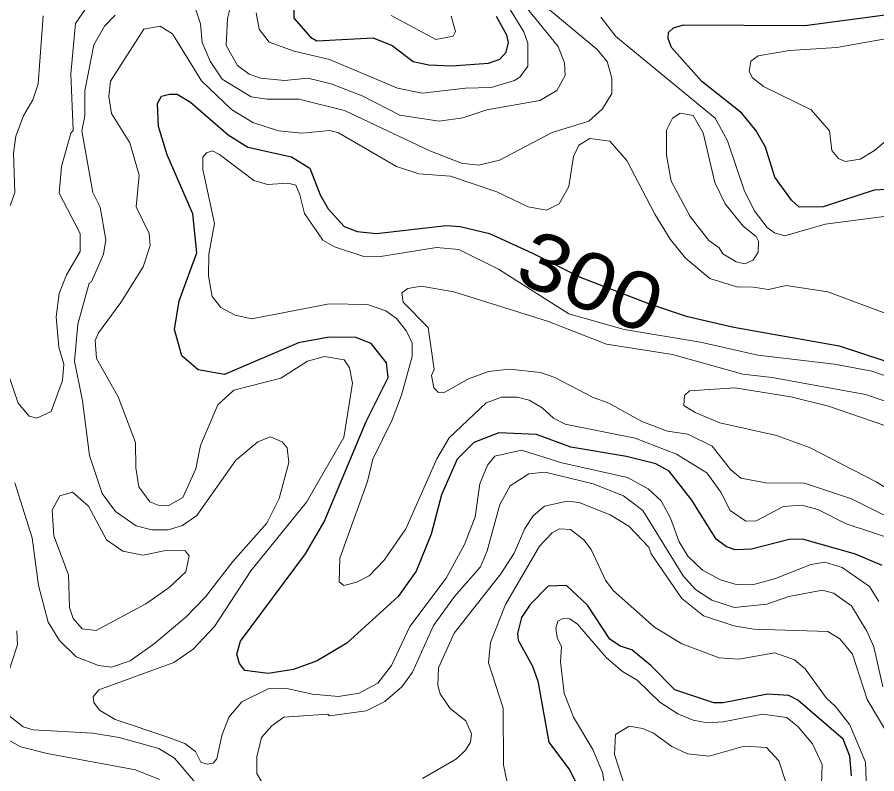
# Model space of a CAD drawing. Extents: x 673.6 to 698.9, y 7012 to 7040.1.
# Drawn here: x 677.012 to 678.22, y 7016.482 to 7017.545 of the extents above; entities that cross this region are included whole.
import ezdxf
from ezdxf.enums import TextEntityAlignment as Align

# ---------------------------------------------------------------- set-up
doc = ezdxf.new("R2010")
doc.units = 0
doc.header["$LTSCALE"] = 0.032
doc.layers.add('1', color=7, linetype='Continuous', lineweight=25)
doc.layers.add('2', color=7, linetype='Continuous', lineweight=13)
doc.layers.add('61', color=7, linetype='Continuous')

msp = doc.modelspace()

# ---------------------------------------------------------------- linework, layer by layer
at = {"layer": '1'}
for points in [[(677.401, 7017.5941), (677.4009, 7017.5438), (677.424, 7017.5172), (677.4332, 7017.5123), (677.5124, 7017.5164), (677.539, 7017.5057), (677.5685, 7017.4832), (677.5907, 7017.4781), (677.6225, 7017.477), (677.6745, 7017.4809), (677.6905, 7017.4863), (677.6991, 7017.496), (677.7025, 7017.5095), (677.7002, 7017.5202), (677.6855, 7017.5465)], [(678.2408, 7017.3035), (678.2165, 7017.302), (678.1451, 7017.2789), (678.111, 7017.2783), (678.1003, 7017.288), (678.0768, 7017.3203), (678.0641, 7017.3627), (678.051, 7017.3857), (678.0304, 7017.4103), (677.9744, 7017.455), (677.9317, 7017.5028), (677.9271, 7017.5152), (677.9277, 7017.5239), (677.9347, 7017.5304), (677.9487, 7017.5344), (678.119, 7017.5338), (678.2393, 7017.5494)], [(678.2277, 7016.7746), (678.1904, 7016.7902), (678.1159, 7016.8113), (678.097, 7016.8112), (678.0444, 7016.7973), (678.0214, 7016.7966), (678.0092, 7016.8007), (677.9943, 7016.8114), (677.9605, 7016.8661), (677.9286, 7016.9072), (677.9096, 7016.9173), (677.8686, 7016.9279), (677.7901, 7016.9408), (677.742, 7016.9585), (677.689, 7016.9608), (677.654, 7016.9473), (677.6304, 7016.9241), (677.6083, 7016.8739), (677.594, 7016.8184), (677.5729, 7016.7665), (677.5474, 7016.731), (677.4751, 7016.6654), (677.4336, 7016.6403), (677.4002, 7016.6284), (677.3647, 7016.6225), (677.3318, 7016.6267), (677.3242, 7016.6366), (677.3204, 7016.65), (677.3256, 7016.6683), (677.4169, 7016.7908), (677.4433, 7016.836), (677.5025, 7016.9771), (677.5334, 7017.039), (677.531, 7017.0595), (677.5094, 7017.0865), (677.4881, 7017.0948), (677.4503, 7017.0957), (677.4073, 7017.0873), (677.3034, 7017.0432), (677.2663, 7017.0497), (677.2433, 7017.0694), (677.2328, 7017.1064), (677.2397, 7017.1466), (677.2645, 7017.2141), (677.2589, 7017.2687), (677.2226, 7017.3516), (677.2102, 7017.3916), (677.2091, 7017.424), (677.2147, 7017.4341), (677.2259, 7017.4371), (677.2366, 7017.4373), (677.2555, 7017.426), (677.3083, 7017.3798), (677.3361, 7017.3624), (677.3973, 7017.3488), (677.4232, 7017.333)], [(677.4232, 7017.333), (677.4379, 7017.2957), (677.4492, 7017.276), (677.4714, 7017.2512), (677.4898, 7017.2442), (677.5169, 7017.2412)], [(677.5169, 7017.2412), (677.6147, 7017.2525), (677.6344, 7017.2511), (677.6759, 7017.241), (677.7363, 7017.2136), (677.8032, 7017.1799), (677.8994, 7017.1427), (677.9525, 7017.125), (678.0192, 7017.1094), (678.1673, 7017.0832), (678.2631, 7017.0518)], [(678.1848, 7016.4786), (678.1825, 7016.5066), (678.1733, 7016.5302), (678.1093, 7016.5853), (678.0967, 7016.5919), (678.0666, 7016.5935), (678.0046, 7016.5813), (677.9914, 7016.5813), (677.9365, 7016.5999), (677.9028, 7016.6341), (677.8761, 7016.6558), (677.8596, 7016.661), (677.8448, 7016.6709), (677.8135, 7016.7185), (677.7839, 7016.7463), (677.7583, 7016.7456), (677.7332, 7016.7198), (677.7207, 7016.7012), (677.715, 7016.6791), (677.7159, 7016.6697), (677.7362, 7016.633), (677.7436, 7016.612), (677.7594, 7016.5263), (677.7882, 7016.4872), (677.8004, 7016.4634)]]:
    msp.add_lwpolyline(points, dxfattribs=at)
at = {"layer": '2'}
for points in [[(677.3476, 7017.5512), (677.3518, 7017.5283), (677.3661, 7017.51), (677.4013, 7017.4975), (677.4509, 7017.4858), (677.5463, 7017.4455), (677.5811, 7017.4384), (677.6419, 7017.4457), (677.6784, 7017.4465), (677.711, 7017.4561), (677.7188, 7017.4613), (677.7298, 7017.4765), (677.7297, 7017.5087), (677.7243, 7017.5248), (677.678, 7017.6002)], [(677.1823, 7017.5567), (677.2343, 7017.5754), (677.2527, 7017.5722), (677.2629, 7017.5556), (677.2694, 7017.5358), (677.2717, 7017.5097)], [(677.3125, 7017.5639), (677.3074, 7017.5435), (677.3058, 7017.5053), (677.3217, 7017.4776), (677.338, 7017.4654), (677.3537, 7017.4597), (677.3875, 7017.4565), (677.4204, 7017.4597), (677.4533, 7017.4516), (677.4967, 7017.4349), (677.5499, 7017.4074), (677.6052, 7017.399), (677.6381, 7017.4039), (677.6722, 7017.4153), (677.7467, 7017.4281), (677.7703, 7017.4422), (677.7822, 7017.4631), (677.7814, 7017.4811), (677.7724, 7017.5041), (677.7086, 7017.5827)], [(677.1134, 7017.5648), (677.0935, 7017.5364), (677.0872, 7017.4659), (677.0904, 7017.386), (677.087, 7017.3821), (677.074, 7017.3352), (677.0706, 7017.2978), (677.1002, 7017.2411), (677.1002, 7017.2157), (677.0811, 7017.1832), (677.0706, 7017.157), (677.0666, 7017.1241), (677.0704, 7017.0812), (677.0771, 7017.0574), (677.0753, 7017.0345), (677.0597, 7016.9909), (677.0394, 7016.9815), (677.0284, 7016.9844), (677.0129, 7017.0026), (676.9995, 7017.0423)], [(677.2717, 7017.5097), (677.2833, 7017.4833), (677.2999, 7017.4582), (677.3406, 7017.4334), (677.3632, 7017.4302), (677.4076, 7017.4301), (677.4721, 7017.4141), (677.5921, 7017.3575), (677.6366, 7017.3401), (677.6602, 7017.3373), (677.6899, 7017.3445), (677.7639, 7017.383), (677.8156, 7017.3993), (677.8348, 7017.4164), (677.8479, 7017.4379), (677.848, 7017.4597), (677.8415, 7017.4832), (677.8269, 7017.5005), (677.7467, 7017.5668)], [(676.8012, 7017.5472), (676.7946, 7017.5254), (676.7913, 7017.4779), (676.7987, 7017.4318), (676.8103, 7017.4084), (676.8378, 7017.377), (676.9033, 7017.328), (676.9545, 7017.2784), (676.9716, 7017.2678), (676.9826, 7017.2668), (677.0023, 7017.2814), (677.0082, 7017.299), (677.0066, 7017.3541), (677.0099, 7017.378), (677.0204, 7017.4068), (677.0339, 7017.4293), (677.0411, 7017.4515), (677.0485, 7017.5472)], [(677.0083, 7016.8907), (677.0329, 7016.8135), (677.0419, 7016.7464), (677.0551, 7016.6947), (677.0711, 7016.6692), (677.0946, 7016.6463), (677.1259, 7016.6338), (677.1442, 7016.6314), (677.1704, 7016.6403), (677.2048, 7016.6646), (677.2493, 7016.7023), (677.2767, 7016.7306), (677.3148, 7016.7799), (677.3627, 7016.8342), (677.3802, 7016.8685), (677.3936, 7016.9191), (677.3912, 7016.94), (677.3845, 7016.9485), (677.3679, 7016.9552), (677.35, 7016.9485), (677.3191, 7016.9226), (677.2643, 7016.8448), (677.2443, 7016.8308), (677.2242, 7016.8245), (677.2009, 7016.8244), (677.1788, 7016.8304), (677.1498, 7016.8505), (677.131, 7016.8757), (677.1134, 7016.9292), (677.1035, 7017.0061), (677.0921, 7017.0616), (677.0971, 7017.1137), (677.113, 7017.1713), (677.1162, 7017.1731), (677.1333, 7017.2122), (677.1364, 7017.2322), (677.1284, 7017.2782), (677.1183, 7017.2989), (677.1028, 7017.3857), (677.1068, 7017.4068), (677.1069, 7017.4419), (677.1196, 7017.5065), (677.1345, 7017.5327), (677.1494, 7017.5482)], [(677.6219, 7017.5468), (677.6278, 7017.5252), (677.6249, 7017.5184), (677.6004, 7017.5141), (677.5374, 7017.5476)], [(677.8324, 7017.5455), (677.8536, 7017.5183), (677.9933, 7017.4032), (678.0105, 7017.3715), (678.0338, 7017.302), (678.0481, 7017.2734), (678.0662, 7017.2498), (678.0766, 7017.2423), (678.091, 7017.2379), (678.1479, 7017.2542), (678.2338, 7017.2658)], [(678.2422, 7017.1257), (678.1515, 7017.1591), (678.093, 7017.1679), (678.0683, 7017.1623), (678.0436, 7017.1663), (678.0252, 7017.1656), (677.9854, 7017.1781), (677.9516, 7017.2066), (677.93, 7017.2332), (677.9081, 7017.2683), (677.869, 7017.3437), (677.8448, 7017.3711), (677.8171, 7017.375), (677.8013, 7017.3652), (677.7939, 7017.3496), (677.7872, 7017.3072), (677.774, 7017.2831), (677.756, 7017.2741), (677.7304, 7017.2788), (677.686, 7017.2999), (677.6209, 7017.3217), (677.5766, 7017.325), (677.5452, 7017.3352), (677.4635, 7017.3827), (677.4514, 7017.3858), (677.412, 7017.3825), (677.3791, 7017.3856), (677.3432, 7017.3974), (677.3133, 7017.4154), (677.271, 7017.456), (677.2302, 7017.522), (677.2126, 7017.5327), (677.19, 7017.5287), (677.143, 7017.4553), (677.1405, 7017.434), (677.1443, 7017.4097), (677.1699, 7017.3687), (677.1831, 7017.3233), (677.1792, 7017.2785), (677.1971, 7017.2414), (677.1988, 7017.2244), (677.1887, 7017.1945), (677.1573, 7017.1443), (677.1259, 7017.1017), (677.1216, 7017.0907), (677.1233, 7017.0653), (677.1536, 7017.0118), (677.1782, 7016.9472), (677.1784, 7016.9117), (677.183, 7016.8851), (677.1984, 7016.8639), (677.21, 7016.8591), (677.2241, 7016.8583), (677.2448, 7016.8699), (677.2628, 7016.9105), (677.2696, 7016.9433), (677.294, 7017.0004), (677.3163, 7017.0208), (677.3826, 7017.0377), (677.4199, 7017.0619), (677.4437, 7017.0685), (677.4713, 7017.0637), (677.479, 7017.0525), (677.4831, 7017.0307), (677.4709, 7016.9542), (677.4184, 7016.8634), (677.3403, 7016.7668), (677.2892, 7016.6888), (677.2591, 7016.6571), (677.2318, 7016.638)], [(678.2567, 7017.3911), (678.2173, 7017.3581), (678.1972, 7017.3456), (678.1757, 7017.3425), (678.1664, 7017.3468), (678.1572, 7017.3578), (678.1537, 7017.3854), (678.1282, 7017.4153), (678.0611, 7017.4479), (678.0457, 7017.4602), (678.0407, 7017.4691), (678.0435, 7017.4833), (678.0538, 7017.491), (678.0978, 7017.4983), (678.1643, 7017.5025), (678.2642, 7017.5206)], [(678.2487, 7016.8096), (678.1772, 7016.8329), (678.1373, 7016.8532), (678.1152, 7016.8591), (678.0893, 7016.8572), (678.0509, 7016.8372), (678.0361, 7016.8369), (678.0141, 7016.8517), (678.0011, 7016.8776), (677.9813, 7016.9047), (677.9388, 7016.9312), (677.8806, 7016.9536), (677.782, 7016.9734), (677.7657, 7016.9816), (677.7497, 7016.996), (677.7317, 7017.0068), (677.7149, 7017.011), (677.6929, 7017.011), (677.6712, 7017.0031), (677.6189, 7016.9541), (677.6017, 7016.9243), (677.5583, 7016.826), (677.5278, 7016.782), (677.5065, 7016.7598), (677.4892, 7016.751), (677.4712, 7016.7465), (677.4644, 7016.7516), (677.4654, 7016.7849), (677.5044, 7016.8924), (677.5119, 7016.9239), (677.5389, 7016.9795), (677.5521, 7017.014), (677.567, 7017.0685), (677.567, 7017.087), (677.5592, 7017.1037), (677.5451, 7017.1216), (677.53, 7017.1326), (677.5045, 7017.1416), (677.4503, 7017.1425), (677.3418, 7017.1212), (677.3182, 7017.1263), (677.2982, 7017.1371), (677.2859, 7017.1526), (677.2806, 7017.1814), (677.281, 7017.212), (677.2892, 7017.2551), (677.2729, 7017.3312), (677.2728, 7017.3484), (677.278, 7017.3545), (677.2862, 7017.3574), (677.296, 7017.3524), (677.3445, 7017.3155), (677.3636, 7017.3102), (677.3922, 7017.3119), (677.4033, 7017.3091), (677.409, 7017.2956), (677.4157, 7017.2693), (677.4415, 7017.2319), (677.458, 7017.2226), (677.4993, 7017.2087)], [(677.4993, 7017.2087), (677.5198, 7017.2083), (677.6012, 7017.2214), (677.6327, 7017.2189), (677.6883, 7017.1912), (677.7873, 7017.1282)], [(678.2945, 7016.9842), (678.2046, 7017.0147), (678.0732, 7017.0389), (678.0322, 7017.0433), (677.9332, 7017.0711), (677.8402, 7017.0858), (677.7576, 7017.1178), (677.6259, 7017.159), (677.5798, 7017.1671), (677.5608, 7017.1639), (677.5524, 7017.158), (677.5546, 7017.1445), (677.5898, 7017.109)], [(677.7873, 7017.1282), (677.8652, 7017.1062), (677.9726, 7017.0883), (678.053, 7017.07), (678.1611, 7017.0577), (678.2133, 7017.0476), (678.3022, 7017.0173)], [(677.5898, 7017.109), (677.5982, 7017.05), (677.5943, 7017.0418), (677.5975, 7017.0243), (677.6043, 7017.0177), (677.6128, 7017.018)], [(677.6128, 7017.018), (677.6461, 7017.037), (677.6742, 7017.0473), (677.7041, 7017.0504), (677.7475, 7017.0456), (677.7678, 7017.0388), (677.8208, 7017.011), (677.8434, 7017.0027), (677.8898, 7016.977), (677.926, 7016.9632), (677.9549, 7016.9592), (677.989, 7016.9421), (678.0148, 7016.9094), (678.0293, 7016.8972), (678.0644, 7016.8906), (678.1189, 7016.8903), (678.1846, 7016.8682), (678.2307, 7016.8452)], [(678.2554, 7016.8701), (678.2193, 7016.8923), (678.1258, 7016.9403), (678.0794, 7016.9573), (677.9997, 7016.9752), (677.9648, 7016.9896), (677.9493, 7016.9996), (677.9501, 7017.0134), (677.9569, 7017.0201), (678.021, 7017.0241), (678.0995, 7017.0118), (678.1525, 7016.9983), (678.2631, 7016.9604)], [(677.1495, 7016.5582), (677.2236, 7016.5331), (677.2475, 7016.5242), (677.2624, 7016.513), (677.2698, 7016.4981), (677.2789, 7016.4951), (677.2875, 7016.4968), (677.2923, 7016.5029), (677.2995, 7016.5355), (677.3094, 7016.5613), (677.3278, 7016.5826), (677.3644, 7016.6009), (677.3911, 7016.6018), (677.427, 7016.5936), (677.4635, 7016.5904), (677.4928, 7016.5952), (677.519, 7016.6091), (677.538, 7016.6341), (677.5636, 7016.6886), (677.615, 7016.7565), (677.6409, 7016.8039), (677.6555, 7016.8431), (677.6624, 7016.8894), (677.6729, 7016.9154), (677.6833, 7016.928), (677.721, 7016.9368), (677.7777, 7016.919), (677.8697, 7016.8983), (677.8988, 7016.8824), (677.9171, 7016.8653), (677.9302, 7016.8412), (677.9424, 7016.8076), (677.9548, 7016.7876), (677.9755, 7016.768), (678.0008, 7016.7545), (678.0226, 7016.748), (678.0457, 7016.7473), (678.0778, 7016.7563), (678.1277, 7016.7761), (678.1475, 7016.7794), (678.1719, 7016.7719), (678.2101, 7016.745), (678.2233, 7016.7238)], [(678.229, 7016.6039), (678.216, 7016.6601), (678.2065, 7016.682), (678.1849, 7016.7176), (678.1596, 7016.7355), (678.1439, 7016.74), (678.0966, 7016.7309), (678.0659, 7016.72), (678.0205, 7016.7156), (677.9883, 7016.7257), (677.9653, 7016.7409), (677.9479, 7016.7599), (677.8915, 7016.8518), (677.8642, 7016.8726), (677.8216, 7016.8892), (677.7543, 7016.9058), (677.731, 7016.9033), (677.705, 7016.8867), (677.6904, 7016.8601), (677.6726, 7016.7953), (677.6631, 7016.7727), (677.6266, 7016.731), (677.5973, 7016.6902), (677.5676, 7016.6245), (677.5525, 7016.6037), (677.5287, 7016.5833), (677.5025, 7016.5701), (677.4508, 7016.5632), (677.4485, 7016.5657)], [(677.5817, 7016.4752), (677.6292, 7016.5026), (677.6422, 7016.5149), (677.6489, 7016.526), (677.6507, 7016.538), (677.6427, 7016.5562), (677.6207, 7016.5736), (677.6065, 7016.594), (677.6032, 7016.606), (677.604, 7016.6304), (677.6263, 7016.6793), (677.6918, 7016.7628), (677.7106, 7016.7919), (677.7255, 7016.8266), (677.7372, 7016.8442), (677.753, 7016.8581), (677.7849, 7016.8647), (677.802, 7016.8631), (677.8454, 7016.8455)], [(677.8454, 7016.8455), (677.8716, 7016.8298), (677.8998, 7016.8004), (677.9032, 7016.7908), (677.9461, 7016.7281), (677.9768, 7016.7039)], [(678.2063, 7016.4477), (678.2047, 7016.4979), (678.1827, 7016.5505), (678.1625, 7016.5765), (678.1491, 7016.5885), (678.1198, 7016.6291), (678.1046, 7016.6419), (678.0769, 7016.6518), (678.0263, 7016.643), (677.9989, 7016.6446), (677.9463, 7016.6644), (677.9078, 7016.6876), (677.8495, 7016.7393), (677.8387, 7016.7539), (677.8186, 7016.7971), (677.8086, 7016.8105), (677.7899, 7016.8251), (677.7743, 7016.8261), (677.7641, 7016.8205), (677.7461, 7016.8018), (677.6983, 7016.7198), (677.6772, 7016.6663), (677.6743, 7016.6376), (677.6951, 7016.5738), (677.6954, 7016.4943), (677.7035, 7016.4557)], [(678.1422, 7016.4526), (678.1438, 7016.4946), (678.1299, 7016.524), (678.11, 7016.5478), (678.0937, 7016.5606), (678.0598, 7016.5655), (678.0046, 7016.5547), (677.9821, 7016.5534), (677.9621, 7016.5572), (677.9406, 7016.5658), (677.9152, 7016.5823), (677.8833, 7016.6133), (677.8628, 7016.6257), (677.8404, 7016.6448), (677.7995, 7016.6922), (677.7886, 7016.6995), (677.7791, 7016.6999), (677.7717, 7016.6962), (677.7693, 7016.6864), (677.7711, 7016.6734), (677.7772, 7016.6601), (677.7758, 7016.6389), (677.7806, 7016.5952), (677.7937, 7016.5611), (677.8211, 7016.516), (677.8348, 7016.4837), (677.8483, 7016.4045)], [(677.9768, 7016.7039), (678.0193, 7016.6897), (678.0473, 7016.6848), (678.1514, 7016.6817), (678.1685, 7016.6716), (678.1863, 7016.65), (678.2068, 7016.586), (678.2372, 7016.535)], [(676.9943, 7016.6088), (677.0123, 7016.663), (677.0114, 7016.6826)], [(677.2318, 7016.638), (677.1265, 7016.5999), (677.1188, 7016.5898), (677.1197, 7016.5819), (677.1276, 7016.5713), (677.1495, 7016.5582)], [(677.3485, 7016.4822), (677.369, 7016.448), (677.4234, 7016.4067), (677.4569, 7016.3914), (677.5001, 7016.3651), (677.5259, 7016.3393), (677.525, 7016.3252), (677.5175, 7016.3167), (677.4641, 7016.2998), (677.417, 7016.2609), (677.4024, 7016.2609), (677.3877, 7016.2693), (677.3633, 7016.2983), (677.2675, 7016.4628), (677.2328, 7016.5038), (677.2111, 7016.5171), (677.1549, 7016.5327), (677.1183, 7016.5387), (677.0344, 7016.5436), (677.0201, 7016.5476), (676.9978, 7016.5655)], [(677.4485, 7016.5657), (677.3866, 7016.5615), (677.3697, 7016.5492), (677.3554, 7016.5329), (677.3489, 7016.5053), (677.3485, 7016.4822)], [(676.9813, 7016.539), (677.0169, 7016.5198), (677.054, 7016.5101), (677.1783, 7016.4873), (677.212, 7016.4736)]]:
    msp.add_lwpolyline(points, dxfattribs=at)
for points in [[(677.9312, 7017.315), (677.958, 7017.2652), (677.9842, 7017.2314), (677.9987, 7017.2209), (678.0041, 7017.2125), (678.0225, 7017.2015), (678.035, 7017.1988), (678.0465, 7017.2038), (678.0535, 7017.2149), (678.0542, 7017.2303), (678.0508, 7017.237), (678.0327, 7017.2516), (678.0074, 7017.283), (677.9928, 7017.3131), (677.9761, 7017.3827), (677.9622, 7017.4069), (677.944, 7017.4103), (677.9332, 7017.4033), (677.9247, 7017.3864), (677.9245, 7017.3512)], [(677.0631, 7016.8161), (677.0608, 7016.8523), (677.0719, 7016.8725), (677.0894, 7016.8778), (677.1119, 7016.8578), (677.1372, 7016.8106), (677.1605, 7016.7948), (677.1883, 7016.7892), (677.2206, 7016.7958), (677.2478, 7016.795), (677.2537, 7016.7882), (677.249, 7016.7655), (677.2256, 7016.7436), (677.1925, 7016.7206), (677.1229, 7016.6832), (677.103, 7016.6855), (677.0904, 7016.7002), (677.0855, 7016.7153), (677.0838, 7016.7612)], [(677.8687, 7016.4145), (677.9023, 7016.2981), (677.919, 7016.2717), (677.9298, 7016.2643), (677.9553, 7016.26), (677.9741, 7016.2651), (677.9968, 7016.2822), (678.0206, 7016.3158), (678.0515, 7016.4071), (678.0732, 7016.4328), (678.0879, 7016.4569), (678.092, 7016.4715), (678.0828, 7016.5001), (678.0655, 7016.5188), (678.0338, 7016.5204), (677.9849, 7016.5065), (677.9544, 7016.5095), (677.932, 7016.5202), (677.9064, 7016.5389), (677.8912, 7016.5455), (677.8724, 7016.5486), (677.8531, 7016.5368), (677.8514, 7016.5089), (677.8661, 7016.4637)]]:
    msp.add_lwpolyline(points, close=True, dxfattribs=at)

# ---------------------------------------------------------------- texts
at = {"layer": '61', "width": 1.15}
msp.add_text('300', height=0.08, rotation=337.86, dxfattribs=at).set_placement((677.8032, 7017.1368), align=Align.CENTER)

doc.saveas('drawing.dxf')
